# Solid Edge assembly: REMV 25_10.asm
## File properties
Title: Zylinder
Author: ahadarics
Template: iso metric assembly.asm
Last saved by: ahadarics
Revision: 2
Application: Solid Edge
Username: ahadarics
Dokumentum tartalom típus: 1
Document Number: REMV 25/10
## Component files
Profilrohr.par
Kolbenstange.par
Kit_1.par
Kit_2.par
Mutter_1.par
Mutter_2.par
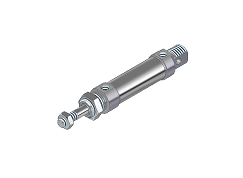
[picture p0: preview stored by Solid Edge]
